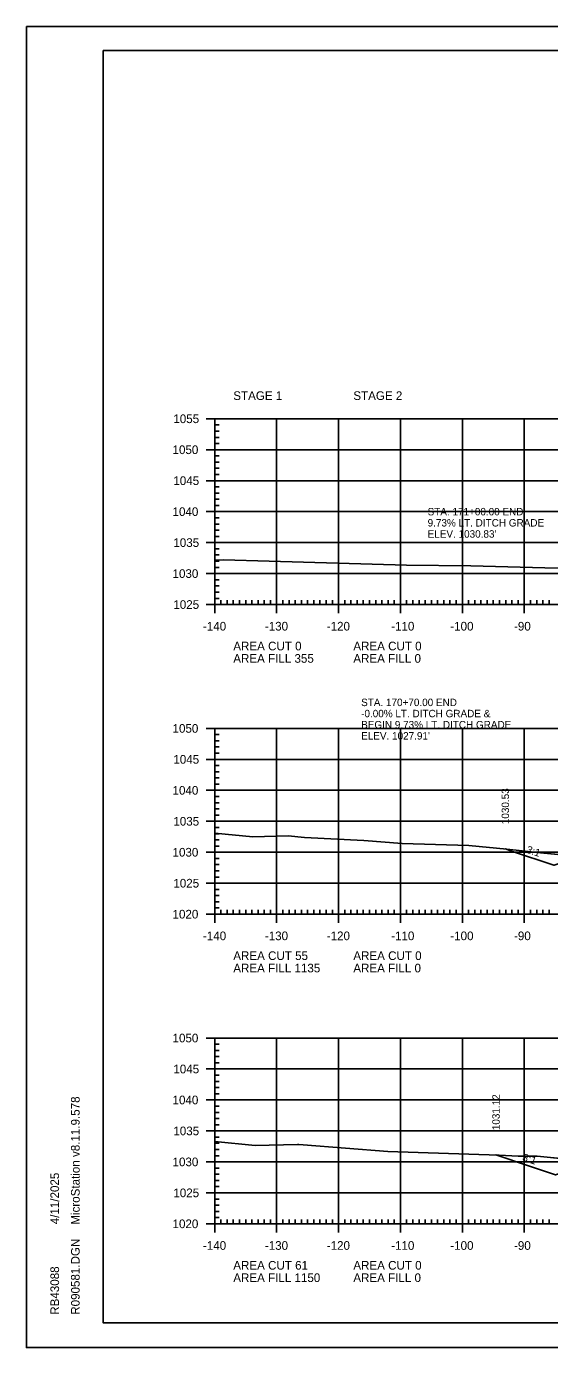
# Model space of a CAD drawing. Extents: x 1322838 to 1324533, y 339903 to 351025.
# Drawn here: x 1323533.3 to 1323617.8, y 346971.9 to 347185.2 of the extents above; entities that cross this region are included whole.
import ezdxf

# ---------------------------------------------------------------- set-up
doc = ezdxf.new("R2010")
doc.units = 0
for name, color, linetype in [('R_Axis', 7, 'Continuous'), ('R_Axis Annot', 7, 'Continuous'), ('R_Border', 7, 'Continuous'), ('R_Drive', 7, 'Continuous'), ('R_Exist Surface', 7, 'Continuous'), ('R_Fin Surface', 7, 'Continuous'), ('R_Fin Surface Annot', 7, 'Continuous'), ('R_Grid', 7, 'Continuous'), ('R_No Plot', 7, 'Continuous')]:
    doc.layers.add(name, color=color, linetype=linetype)

msp = doc.modelspace()

# ---------------------------------------------------------------- linework, layer by layer
at = {"layer": 'R_Axis'}
for p, q in [((1323562.32, 347121.84), (1323565.12, 347121.84)), ((1323563.72, 347091.84), (1323563.72, 347121.84)), ((1323563.72, 347120.84), (1323564.42, 347120.84)), ((1323563.72, 347119.84), (1323564.42, 347119.84)), ((1323563.72, 347118.84), (1323564.42, 347118.84)), ((1323563.72, 347117.84), (1323564.42, 347117.84)), ((1323562.32, 347116.84), (1323565.12, 347116.84)), ((1323563.72, 347115.84), (1323564.42, 347115.84)), ((1323563.72, 347114.84), (1323564.42, 347114.84)), ((1323563.72, 347113.84), (1323564.42, 347113.84)), ((1323562.32, 347111.84), (1323565.12, 347111.84)), ((1323563.72, 347112.84), (1323564.42, 347112.84)), ((1323563.72, 347110.84), (1323564.42, 347110.84)), ((1323563.72, 347109.84), (1323564.42, 347109.84)), ((1323563.72, 347108.84), (1323564.42, 347108.84)), ((1323562.32, 347106.84), (1323565.12, 347106.84)), ((1323563.72, 347107.84), (1323564.42, 347107.84)), ((1323563.72, 347105.84), (1323564.42, 347105.84)), ((1323563.72, 347104.84), (1323564.42, 347104.84)), ((1323563.72, 347103.84), (1323564.42, 347103.84)), ((1323563.72, 347102.84), (1323564.42, 347102.84)), ((1323562.32, 347101.84), (1323565.12, 347101.84)), ((1323563.72, 347100.84), (1323564.42, 347100.84)), ((1323563.72, 347099.84), (1323564.42, 347099.84)), ((1323563.72, 347098.84), (1323564.42, 347098.84)), ((1323562.32, 347096.84), (1323565.12, 347096.84)), ((1323563.72, 347097.84), (1323564.42, 347097.84)), ((1323563.72, 347095.84), (1323564.42, 347095.84)), ((1323563.72, 347094.84), (1323564.42, 347094.84)), ((1323562.32, 347091.84), (1323565.12, 347091.84)), ((1323563.72, 347093.84), (1323564.42, 347093.84)), ((1323563.72, 347090.44), (1323563.72, 347093.24)), ((1323563.72, 347092.84), (1323564.42, 347092.84)), ((1323563.72, 347091.84), (1323843.72, 347091.84)), ((1323564.72, 347091.84), (1323564.72, 347092.54)), ((1323565.72, 347091.84), (1323565.72, 347092.54)), ((1323566.72, 347091.84), (1323566.72, 347092.54)), ((1323567.72, 347091.84), (1323567.72, 347092.54)), ((1323568.72, 347091.84), (1323568.72, 347092.54)), ((1323569.72, 347091.84), (1323569.72, 347092.54)), ((1323570.72, 347091.84), (1323570.72, 347092.54)), ((1323571.72, 347091.84), (1323571.72, 347092.54)), ((1323572.72, 347091.84), (1323572.72, 347092.54)), ((1323573.72, 347090.44), (1323573.72, 347093.24)), ((1323574.72, 347091.84), (1323574.72, 347092.54)), ((1323575.72, 347091.84), (1323575.72, 347092.54)), ((1323576.72, 347091.84), (1323576.72, 347092.54)), ((1323577.72, 347091.84), (1323577.72, 347092.54)), ((1323578.72, 347091.84), (1323578.72, 347092.54)), ((1323579.72, 347091.84), (1323579.72, 347092.54)), ((1323580.72, 347091.84), (1323580.72, 347092.54)), ((1323581.72, 347091.84), (1323581.72, 347092.54)), ((1323582.72, 347091.84), (1323582.72, 347092.54)), ((1323583.72, 347090.44), (1323583.72, 347093.24)), ((1323584.72, 347091.84), (1323584.72, 347092.54)), ((1323585.72, 347091.84), (1323585.72, 347092.54)), ((1323586.72, 347091.84), (1323586.72, 347092.54)), ((1323587.72, 347091.84), (1323587.72, 347092.54)), ((1323588.72, 347091.84), (1323588.72, 347092.54)), ((1323589.72, 347091.84), (1323589.72, 347092.54)), ((1323590.72, 347091.84), (1323590.72, 347092.54)), ((1323591.72, 347091.84), (1323591.72, 347092.54)), ((1323592.72, 347091.84), (1323592.72, 347092.54)), ((1323593.72, 347090.44), (1323593.72, 347093.24)), ((1323594.72, 347091.84), (1323594.72, 347092.54)), ((1323595.72, 347091.84), (1323595.72, 347092.54)), ((1323596.72, 347091.84), (1323596.72, 347092.54)), ((1323597.72, 347091.84), (1323597.72, 347092.54)), ((1323598.72, 347091.84), (1323598.72, 347092.54)), ((1323599.72, 347091.84), (1323599.72, 347092.54)), ((1323600.72, 347091.84), (1323600.72, 347092.54)), ((1323601.72, 347091.84), (1323601.72, 347092.54)), ((1323602.72, 347091.84), (1323602.72, 347092.54)), ((1323603.72, 347090.44), (1323603.72, 347093.24)), ((1323604.72, 347091.84), (1323604.72, 347092.54)), ((1323605.72, 347091.84), (1323605.72, 347092.54)), ((1323606.72, 347091.84), (1323606.72, 347092.54)), ((1323607.72, 347091.84), (1323607.72, 347092.54)), ((1323608.72, 347091.84), (1323608.72, 347092.54)), ((1323609.72, 347091.84), (1323609.72, 347092.54)), ((1323610.72, 347091.84), (1323610.72, 347092.54)), ((1323611.72, 347091.84), (1323611.72, 347092.54)), ((1323612.72, 347091.84), (1323612.72, 347092.54)), ((1323613.72, 347090.44), (1323613.72, 347093.24)), ((1323614.72, 347091.84), (1323614.72, 347092.54)), ((1323615.72, 347091.84), (1323615.72, 347092.54)), ((1323616.72, 347091.84), (1323616.72, 347092.54)), ((1323617.72, 347091.84), (1323617.72, 347092.54)), ((1323562.32, 347071.84), (1323565.12, 347071.84)), ((1323563.72, 347041.84), (1323563.72, 347071.84)), ((1323563.72, 347070.84), (1323564.42, 347070.84)), ((1323563.72, 347069.84), (1323564.42, 347069.84)), ((1323563.72, 347068.84), (1323564.42, 347068.84)), ((1323562.32, 347066.84), (1323565.12, 347066.84)), ((1323563.72, 347067.84), (1323564.42, 347067.84)), ((1323563.72, 347065.84), (1323564.42, 347065.84)), ((1323563.72, 347064.84), (1323564.42, 347064.84)), ((1323563.72, 347063.84), (1323564.42, 347063.84)), ((1323563.72, 347062.84), (1323564.42, 347062.84)), ((1323562.32, 347061.84), (1323565.12, 347061.84)), ((1323563.72, 347060.84), (1323564.42, 347060.84)), ((1323563.72, 347059.84), (1323564.42, 347059.84)), ((1323563.72, 347058.84), (1323564.42, 347058.84)), ((1323563.72, 347057.84), (1323564.42, 347057.84)), ((1323562.32, 347056.84), (1323565.12, 347056.84)), ((1323563.72, 347055.84), (1323564.42, 347055.84)), ((1323563.72, 347054.84), (1323564.42, 347054.84)), ((1323563.72, 347053.84), (1323564.42, 347053.84)), ((1323562.32, 347051.84), (1323565.12, 347051.84)), ((1323563.72, 347052.84), (1323564.42, 347052.84)), ((1323563.72, 347050.84), (1323564.42, 347050.84)), ((1323563.72, 347049.84), (1323564.42, 347049.84)), ((1323563.72, 347048.84), (1323564.42, 347048.84)), ((1323563.72, 347047.84), (1323564.42, 347047.84)), ((1323562.32, 347046.84), (1323565.12, 347046.84)), ((1323563.72, 347045.84), (1323564.42, 347045.84)), ((1323563.72, 347044.84), (1323564.42, 347044.84)), ((1323563.72, 347043.84), (1323564.42, 347043.84)), ((1323563.72, 347040.44), (1323563.72, 347043.24)), ((1323563.72, 347042.84), (1323564.42, 347042.84)), ((1323573.72, 347040.44), (1323573.72, 347043.24)), ((1323583.72, 347040.44), (1323583.72, 347043.24)), ((1323593.72, 347040.44), (1323593.72, 347043.24)), ((1323603.72, 347040.44), (1323603.72, 347043.24)), ((1323613.72, 347040.44), (1323613.72, 347043.24)), ((1323562.32, 347041.84), (1323565.12, 347041.84)), ((1323563.72, 347041.84), (1323843.72, 347041.84)), ((1323564.72, 347041.84), (1323564.72, 347042.54)), ((1323565.72, 347041.84), (1323565.72, 347042.54)), ((1323566.72, 347041.84), (1323566.72, 347042.54)), ((1323567.72, 347041.84), (1323567.72, 347042.54)), ((1323568.72, 347041.84), (1323568.72, 347042.54)), ((1323569.72, 347041.84), (1323569.72, 347042.54)), ((1323570.72, 347041.84), (1323570.72, 347042.54)), ((1323571.72, 347041.84), (1323571.72, 347042.54)), ((1323572.72, 347041.84), (1323572.72, 347042.54)), ((1323574.72, 347041.84), (1323574.72, 347042.54)), ((1323575.72, 347041.84), (1323575.72, 347042.54)), ((1323576.72, 347041.84), (1323576.72, 347042.54)), ((1323577.72, 347041.84), (1323577.72, 347042.54)), ((1323578.72, 347041.84), (1323578.72, 347042.54)), ((1323579.72, 347041.84), (1323579.72, 347042.54)), ((1323580.72, 347041.84), (1323580.72, 347042.54)), ((1323581.72, 347041.84), (1323581.72, 347042.54)), ((1323582.72, 347041.84), (1323582.72, 347042.54)), ((1323584.72, 347041.84), (1323584.72, 347042.54)), ((1323585.72, 347041.84), (1323585.72, 347042.54)), ((1323586.72, 347041.84), (1323586.72, 347042.54)), ((1323587.72, 347041.84), (1323587.72, 347042.54)), ((1323588.72, 347041.84), (1323588.72, 347042.54)), ((1323589.72, 347041.84), (1323589.72, 347042.54)), ((1323590.72, 347041.84), (1323590.72, 347042.54)), ((1323591.72, 347041.84), (1323591.72, 347042.54)), ((1323592.72, 347041.84), (1323592.72, 347042.54)), ((1323594.72, 347041.84), (1323594.72, 347042.54)), ((1323595.72, 347041.84), (1323595.72, 347042.54)), ((1323596.72, 347041.84), (1323596.72, 347042.54)), ((1323597.72, 347041.84), (1323597.72, 347042.54)), ((1323598.72, 347041.84), (1323598.72, 347042.54)), ((1323599.72, 347041.84), (1323599.72, 347042.54)), ((1323600.72, 347041.84), (1323600.72, 347042.54)), ((1323601.72, 347041.84), (1323601.72, 347042.54)), ((1323602.72, 347041.84), (1323602.72, 347042.54)), ((1323604.72, 347041.84), (1323604.72, 347042.54)), ((1323605.72, 347041.84), (1323605.72, 347042.54)), ((1323606.72, 347041.84), (1323606.72, 347042.54)), ((1323607.72, 347041.84), (1323607.72, 347042.54)), ((1323608.72, 347041.84), (1323608.72, 347042.54)), ((1323609.72, 347041.84), (1323609.72, 347042.54)), ((1323610.72, 347041.84), (1323610.72, 347042.54)), ((1323611.72, 347041.84), (1323611.72, 347042.54)), ((1323612.72, 347041.84), (1323612.72, 347042.54)), ((1323614.72, 347041.84), (1323614.72, 347042.54)), ((1323615.72, 347041.84), (1323615.72, 347042.54)), ((1323616.72, 347041.84), (1323616.72, 347042.54)), ((1323617.72, 347041.84), (1323617.72, 347042.54)), ((1323562.32, 347021.84), (1323565.12, 347021.84)), ((1323563.72, 346991.84), (1323563.72, 347021.84)), ((1323563.72, 347020.84), (1323564.42, 347020.84)), ((1323563.72, 347019.84), (1323564.42, 347019.84)), ((1323563.72, 347018.84), (1323564.42, 347018.84)), ((1323563.72, 347017.84), (1323564.42, 347017.84)), ((1323562.32, 347016.84), (1323565.12, 347016.84)), ((1323563.72, 347015.84), (1323564.42, 347015.84)), ((1323563.72, 347014.84), (1323564.42, 347014.84)), ((1323563.72, 347013.84), (1323564.42, 347013.84)), ((1323563.72, 347012.84), (1323564.42, 347012.84)), ((1323562.32, 347011.84), (1323565.12, 347011.84)), ((1323563.72, 347010.84), (1323564.42, 347010.84)), ((1323563.72, 347009.84), (1323564.42, 347009.84)), ((1323563.72, 347008.84), (1323564.42, 347008.84)), ((1323562.32, 347006.84), (1323565.12, 347006.84)), ((1323563.72, 347007.84), (1323564.42, 347007.84)), ((1323563.72, 347005.84), (1323564.42, 347005.84)), ((1323563.72, 347004.84), (1323564.42, 347004.84)), ((1323563.72, 347003.84), (1323564.42, 347003.84)), ((1323563.72, 347002.84), (1323564.42, 347002.84)), ((1323562.32, 347001.84), (1323565.12, 347001.84)), ((1323563.72, 347000.84), (1323564.42, 347000.84)), ((1323563.72, 346999.84), (1323564.42, 346999.84)), ((1323563.72, 346998.84), (1323564.42, 346998.84)), ((1323562.32, 346996.84), (1323565.12, 346996.84)), ((1323563.72, 346997.84), (1323564.42, 346997.84)), ((1323563.72, 346995.84), (1323564.42, 346995.84)), ((1323563.72, 346994.84), (1323564.42, 346994.84)), ((1323563.72, 346993.84), (1323564.42, 346993.84)), ((1323562.32, 346991.84), (1323565.12, 346991.84)), ((1323563.72, 346990.44), (1323563.72, 346993.24)), ((1323563.72, 346992.84), (1323564.42, 346992.84)), ((1323563.72, 346991.84), (1323843.72, 346991.84)), ((1323564.72, 346991.84), (1323564.72, 346992.54)), ((1323565.72, 346991.84), (1323565.72, 346992.54)), ((1323566.72, 346991.84), (1323566.72, 346992.54)), ((1323567.72, 346991.84), (1323567.72, 346992.54)), ((1323568.72, 346991.84), (1323568.72, 346992.54)), ((1323569.72, 346991.84), (1323569.72, 346992.54)), ((1323570.72, 346991.84), (1323570.72, 346992.54)), ((1323571.72, 346991.84), (1323571.72, 346992.54)), ((1323572.72, 346991.84), (1323572.72, 346992.54)), ((1323573.72, 346990.44), (1323573.72, 346993.24)), ((1323574.72, 346991.84), (1323574.72, 346992.54)), ((1323575.72, 346991.84), (1323575.72, 346992.54)), ((1323576.72, 346991.84), (1323576.72, 346992.54)), ((1323577.72, 346991.84), (1323577.72, 346992.54)), ((1323578.72, 346991.84), (1323578.72, 346992.54)), ((1323579.72, 346991.84), (1323579.72, 346992.54)), ((1323580.72, 346991.84), (1323580.72, 346992.54)), ((1323581.72, 346991.84), (1323581.72, 346992.54)), ((1323582.72, 346991.84), (1323582.72, 346992.54)), ((1323583.72, 346990.44), (1323583.72, 346993.24)), ((1323584.72, 346991.84), (1323584.72, 346992.54)), ((1323585.72, 346991.84), (1323585.72, 346992.54)), ((1323586.72, 346991.84), (1323586.72, 346992.54)), ((1323587.72, 346991.84), (1323587.72, 346992.54)), ((1323588.72, 346991.84), (1323588.72, 346992.54)), ((1323589.72, 346991.84), (1323589.72, 346992.54)), ((1323590.72, 346991.84), (1323590.72, 346992.54)), ((1323591.72, 346991.84), (1323591.72, 346992.54)), ((1323592.72, 346991.84), (1323592.72, 346992.54)), ((1323593.72, 346990.44), (1323593.72, 346993.24)), ((1323594.72, 346991.84), (1323594.72, 346992.54)), ((1323595.72, 346991.84), (1323595.72, 346992.54)), ((1323596.72, 346991.84), (1323596.72, 346992.54)), ((1323597.72, 346991.84), (1323597.72, 346992.54)), ((1323598.72, 346991.84), (1323598.72, 346992.54)), ((1323599.72, 346991.84), (1323599.72, 346992.54)), ((1323600.72, 346991.84), (1323600.72, 346992.54)), ((1323601.72, 346991.84), (1323601.72, 346992.54)), ((1323602.72, 346991.84), (1323602.72, 346992.54)), ((1323603.72, 346990.44), (1323603.72, 346993.24)), ((1323604.72, 346991.84), (1323604.72, 346992.54)), ((1323605.72, 346991.84), (1323605.72, 346992.54)), ((1323606.72, 346991.84), (1323606.72, 346992.54)), ((1323607.72, 346991.84), (1323607.72, 346992.54)), ((1323608.72, 346991.84), (1323608.72, 346992.54)), ((1323609.72, 346991.84), (1323609.72, 346992.54)), ((1323610.72, 346991.84), (1323610.72, 346992.54)), ((1323611.72, 346991.84), (1323611.72, 346992.54)), ((1323612.72, 346991.84), (1323612.72, 346992.54)), ((1323613.72, 346990.44), (1323613.72, 346993.24)), ((1323614.72, 346991.84), (1323614.72, 346992.54)), ((1323615.72, 346991.84), (1323615.72, 346992.54)), ((1323616.72, 346991.84), (1323616.72, 346992.54)), ((1323617.72, 346991.84), (1323617.72, 346992.54))]:
    msp.add_line(p, q, dxfattribs=at)
at = {"layer": 'R_Border'}
for p, q in [((1323545.72, 347181.3), (1323861.9, 347181.3)), ((1323545.72, 346975.84), (1323545.72, 347181.3)), ((1323545.72, 346975.84), (1323545.72, 346975.84)), ((1323861.9, 346975.84), (1323545.72, 346975.84))]:
    msp.add_line(p, q, dxfattribs=at)
at = {"layer": 'R_Exist Surface'}
for points in [[(1323563.72, 347099.01), (1323565.13, 347099.04), (1323572.51, 347098.86), (1323594.68, 347098.22), (1323605.06, 347098.07), (1323617.06, 347097.79), (1323628.3, 347097.73)], [(1323563.72, 347054.94), (1323569.85, 347054.34), (1323575.58, 347054.49), (1323578.2, 347054.23), (1323587.8, 347053.75), (1323594, 347053.26), (1323604.78, 347052.91), (1323610.91, 347052.34), (1323616.33, 347051.77), (1323624.76, 347050.94)], [(1323563.72, 347005.11), (1323570.28, 347004.47), (1323577.09, 347004.66), (1323577.29, 347004.64), (1323577.99, 347004.6), (1323591.7, 347003.52), (1323609.67, 347002.94), (1323612.72, 347002.79), (1323615.82, 347002.74), (1323625.92, 347001.75)]]:
    msp.add_lwpolyline(points, dxfattribs=at)
at = {"layer": 'R_Fin Surface'}
for points in [[(1323610.66, 347052.37), (1323611.68, 347052.03), (1323618.51, 347049.75)], [(1323609.15, 347002.96), (1323614.57, 347001.15), (1323618.78, 346999.75), (1323618.78, 346999.75), (1323637.72, 347006.06), (1323644.22, 347008.23), (1323660.27, 347009.22), (1323666.22, 347009.58), (1323670.88, 347009.98), (1323672.22, 347010.1), (1323672.37, 347010.11), (1323674.22, 347010.27), (1323674.22, 347010.27), (1323703.72, 347012.81), (1323720.85, 347014.28), (1323733.22, 347015.34), (1323735.22, 347015.51), (1323741.22, 347016.03), (1323749.44, 347013.97), (1323753.18, 347013.04), (1323763.22, 347010.53)]]:
    msp.add_lwpolyline(points, dxfattribs=at)
at = {"layer": 'R_Grid'}
for p, q in [((1323563.72, 347121.84), (1323843.72, 347121.84)), ((1323563.72, 347091.84), (1323563.72, 347121.84)), ((1323573.72, 347091.84), (1323573.72, 347121.84)), ((1323583.72, 347091.84), (1323583.72, 347121.84)), ((1323593.72, 347091.84), (1323593.72, 347121.84)), ((1323603.72, 347091.84), (1323603.72, 347121.84)), ((1323613.72, 347091.84), (1323613.72, 347121.84)), ((1323563.72, 347116.84), (1323843.72, 347116.84)), ((1323563.72, 347111.84), (1323843.72, 347111.84)), ((1323563.72, 347106.84), (1323843.72, 347106.84)), ((1323563.72, 347101.84), (1323843.72, 347101.84)), ((1323563.72, 347096.84), (1323843.72, 347096.84)), ((1323563.72, 347091.84), (1323843.72, 347091.84)), ((1323563.72, 347071.84), (1323843.72, 347071.84)), ((1323563.72, 347041.84), (1323563.72, 347071.84)), ((1323573.72, 347041.84), (1323573.72, 347071.84)), ((1323583.72, 347041.84), (1323583.72, 347071.84)), ((1323593.72, 347041.84), (1323593.72, 347071.84)), ((1323603.72, 347041.84), (1323603.72, 347071.84)), ((1323613.72, 347041.84), (1323613.72, 347071.84)), ((1323563.72, 347066.84), (1323843.72, 347066.84)), ((1323563.72, 347061.84), (1323843.72, 347061.84)), ((1323563.72, 347056.84), (1323843.72, 347056.84)), ((1323563.72, 347051.84), (1323843.72, 347051.84)), ((1323563.72, 347046.84), (1323843.72, 347046.84)), ((1323563.72, 347041.84), (1323843.72, 347041.84)), ((1323563.72, 347021.84), (1323843.72, 347021.84)), ((1323563.72, 346991.84), (1323563.72, 347021.84)), ((1323573.72, 346991.84), (1323573.72, 347021.84)), ((1323583.72, 346991.84), (1323583.72, 347021.84)), ((1323593.72, 346991.84), (1323593.72, 347021.84)), ((1323603.72, 346991.84), (1323603.72, 347021.84)), ((1323613.72, 346991.84), (1323613.72, 347021.84)), ((1323563.72, 347016.84), (1323843.72, 347016.84)), ((1323563.72, 347011.84), (1323843.72, 347011.84)), ((1323563.72, 347006.84), (1323843.72, 347006.84)), ((1323563.72, 347001.84), (1323843.72, 347001.84)), ((1323563.72, 346996.84), (1323843.72, 346996.84)), ((1323563.72, 346991.84), (1323843.72, 346991.84))]:
    msp.add_line(p, q, dxfattribs=at)
at = {"layer": 'R_No Plot'}
for p, q in [((1323533.31, 347185.19), (1323866.65, 347185.19)), ((1323533.31, 346971.86), (1323866.65, 346971.86))]:
    msp.add_line(p, q, dxfattribs=at)
for points in [[(1323533.31, 347185.19), (1323866.65, 347185.19), (1323866.65, 346971.86), (1323533.31, 346971.86)], [(1323779.64, 347181.3), (1323799.26, 347181.3), (1323799.26, 347171.42), (1323815.37, 347171.42), (1323838.57, 347171.42), (1323838.57, 347138.75), (1323861.77, 347138.75), (1323861.9, 346975.84), (1323545.72, 346975.84), (1323545.72, 347181.3)], [(1323610.66, 347052.37), (1323610.91, 347052.34), (1323616.33, 347051.77), (1323622.7, 347051.15), (1323622.27, 347051), (1323618.52, 347049.75), (1323618.51, 347049.75), (1323611.68, 347052.03)], [(1323609.15, 347002.96), (1323609.67, 347002.94), (1323612.72, 347002.79), (1323615.82, 347002.74), (1323625.05, 347001.84), (1323618.78, 346999.75), (1323618.78, 346999.75), (1323614.57, 347001.15), (1323609.15, 347002.96)]]:
    msp.add_lwpolyline(points, close=True, dxfattribs=at)

# ---------------------------------------------------------------- texts
at = {"layer": 'R_Axis Annot'}
for s, p in [('STAGE 1', (1323566.72, 347124.87)), ('STAGE 2', (1323586.11, 347124.87)), ('1055', (1323557.04, 347121.14)), ('1050', (1323556.91, 347116.14)), ('1045', (1323557.04, 347111.14)), ('1040', (1323556.91, 347106.14)), ('1035', (1323557.04, 347101.14)), ('1030', (1323556.91, 347096.14)), ('1025', (1323557.04, 347091.14)), ('-140', (1323561.82, 347087.64)), ('-130', (1323571.82, 347087.64)), ('-120', (1323581.82, 347087.64)), ('-110', (1323592.22, 347087.64)), ('-100', (1323601.77, 347087.64)), ('-90', (1323612.06, 347087.64)), ('AREA CUT 0', (1323566.72, 347084.44)), ('AREA CUT 0', (1323586.11, 347084.44)), ('AREA FILL 355', (1323566.72, 347082.44)), ('AREA FILL 0', (1323586.11, 347082.44)), ('1050', (1323556.91, 347071.14)), ('1045', (1323557.04, 347066.14)), ('1040', (1323556.91, 347061.14)), ('1035', (1323557.04, 347056.14)), ('1030', (1323556.91, 347051.14)), ('1025', (1323557.04, 347046.14)), ('1020', (1323556.91, 347041.14)), ('-140', (1323561.82, 347037.64)), ('-130', (1323571.82, 347037.64)), ('-120', (1323581.82, 347037.64)), ('-110', (1323592.22, 347037.64)), ('-100', (1323601.77, 347037.64)), ('-90', (1323612.06, 347037.64)), ('AREA CUT 55', (1323566.72, 347034.44)), ('AREA CUT 0', (1323586.11, 347034.44)), ('AREA FILL 1135', (1323566.72, 347032.44)), ('AREA FILL 0', (1323586.11, 347032.44)), ('1050', (1323556.91, 347021.14)), ('1045', (1323557.04, 347016.14)), ('1040', (1323556.91, 347011.14)), ('1035', (1323557.04, 347006.14)), ('1030', (1323556.91, 347001.14)), ('1025', (1323557.04, 346996.14)), ('1020', (1323556.91, 346991.14)), ('-140', (1323561.82, 346987.64)), ('-130', (1323571.82, 346987.64)), ('-120', (1323581.82, 346987.64)), ('-110', (1323592.22, 346987.64)), ('-100', (1323601.77, 346987.64)), ('-90', (1323612.06, 346987.64)), ('AREA CUT 61', (1323566.72, 346984.44)), ('AREA CUT 0', (1323586.11, 346984.44)), ('AREA FILL 1150', (1323566.72, 346982.44)), ('AREA FILL 0', (1323586.11, 346982.44))]:
    msp.add_text(s, height=1.4, dxfattribs=at).set_placement(p)
at = {"layer": 'R_Border'}
for s, p in [('MicroStation v8.11.9.578', (1323541.91, 346991.7)), ('4/11/2025', (1323538.58, 346991.77)), ('R090581.DGN', (1323541.91, 346977.16)), ('RB43088', (1323538.58, 346977.16))]:
    msp.add_text(s, height=1.4, rotation=90, dxfattribs=at).set_placement(p)
at = {"layer": 'R_Drive'}
for s, p in [('STA. 171+00.00 END', (1323598.11, 347106.24)), ('9.73% LT. DITCH GRADE', (1323598.11, 347104.44)), ("ELEV. 1030.83'", (1323598.11, 347102.64)), ('STA. 170+70.00 END ', (1323587.37, 347075.44)), ('-0.00% LT. DITCH GRADE &', (1323587.37, 347073.64)), ('BEGIN 9.73% LT. DITCH GRADE', (1323587.37, 347071.84)), ("ELEV. 1027.91'", (1323587.37, 347070.04))]:
    msp.add_text(s, height=1.2, dxfattribs=at).set_placement(p)
at = {"layer": 'R_Fin Surface Annot'}
for s, rotation, p in [('1030.53', 90, (1323611.26, 347056.37)), ('3:1', 341.5663, (1323613.96, 347051.79)), ('1031.12', 90, (1323609.75, 347006.96)), ('3:1', 341.5686, (1323613.33, 347002.09))]:
    msp.add_text(s, height=1.2, rotation=rotation, dxfattribs=at).set_placement(p)

doc.saveas('drawing.dxf')
